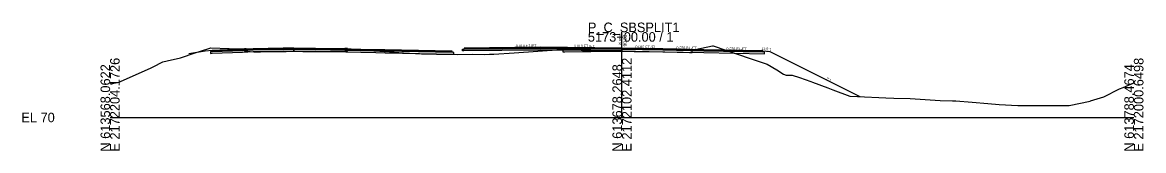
# Model space of a CAD drawing. Extents: x -26 to 1303, y -3010 to 12023.
# Drawn here: x -25.7 to 302.8, y 990.3 to 1027.8 of the extents above; entities that cross this region are included whole.
import ezdxf

# ---------------------------------------------------------------- set-up
doc = ezdxf.new("R2010")
doc.units = 0
for name, color, linetype in [('RD_GPK_XS_Cell', 7, 'Continuous'), ('RD_XS_Base', 7, 'Continuous'), ('RD_XS_ExGround', 7, 'Continuous'), ('RD_XS_ExPaveRet', 7, 'Continuous'), ('RD_XS_Greenside', 7, 'Continuous'), ('RD_XS_Pave', 7, 'Continuous'), ('RD_XS_PaveOvlay_CP', 7, 'Continuous'), ('RD_XS_TieSlope', 7, 'Continuous'), ('RD_XS_TX_Elev_EX', 7, 'Continuous'), ('RD_XS_TX_Elev_PR', 7, 'Continuous'), ('RD_XS_TX_ShdSlope', 7, 'Continuous'), ('RD_XS_TX_Slope', 7, 'Continuous')]:
    doc.layers.add(name, color=color, linetype=linetype)

msp = doc.modelspace()

# ---------------------------------------------------------------- linework, layer by layer
at = {"layer": 'RD_GPK_XS_Cell'}
for p, q in [((150, 1000), (150, 1025)), ((0, 1000), (150, 1000)), ((150, 1000), (300, 1000))]:
    msp.add_line(p, q, dxfattribs=at)
at = {"layer": 'RD_XS_Base'}
for p, q in [((29.75, 1019.29), (29.38, 1019.28)), ((29.38, 1019.28), (29.38, 1019.15)), ((29.38, 1019.15), (29.38, 1018.78)), ((29.38, 1018.78), (29.75, 1018.79)), ((29.88, 1019.3), (29.75, 1019.29)), ((29.75, 1018.79), (29.88, 1018.8)), ((38.75, 1019.65), (29.88, 1019.3)), ((29.88, 1018.8), (38.75, 1019.15)), ((41.88, 1019.78), (38.75, 1019.65)), ((38.75, 1019.15), (41.88, 1019.28)), ((50.75, 1019.95), (41.88, 1019.78)), ((41.88, 1019.28), (50.75, 1019.45)), ((53.88, 1020.02), (50.75, 1019.95)), ((50.75, 1019.45), (53.88, 1019.52)), ((53.88, 1020.13), (53.88, 1020.17)), ((53.88, 1020.17), (53.88, 1020)), ((53.88, 1020.02), (53.88, 1020.13)), ((53.88, 1019.89), (53.88, 1020.02)), ((60.14, 1019.89), (53.88, 1020.02)), ((53.88, 1020), (53.88, 1019.52)), ((53.88, 1019.52), (53.88, 1019.89)), ((53.88, 1019.52), (60.14, 1019.39)), ((77.88, 1019.54), (60.14, 1019.89)), ((60.14, 1019.39), (77.88, 1019.04)), ((80.5, 1019.48), (77.89, 1019.54)), ((77.9, 1019.04), (80.64, 1018.98)), ((100.23, 1019.09), (80.5, 1019.48)), ((80.64, 1018.98), (100.72, 1018.58)), ((100.36, 1019.09), (100.23, 1019.09)), ((100.72, 1019.08), (100.36, 1019.09)), ((100.72, 1018.94), (100.72, 1019.08)), ((100.72, 1018.58), (100.72, 1018.94)), ((103.22, 1019.52), (103.22, 1020.02)), ((103.22, 1020.02), (103.71, 1020.02)), ((103.7, 1019.52), (103.22, 1019.52)), ((125.98, 1019.75), (103.7, 1019.52)), ((103.71, 1020.02), (125.99, 1020.25)), ((126, 1020.25), (150, 1020.01)), ((126, 1020.25), (126, 1020.25)), ((126, 1020.25), (126, 1020.25)), ((150, 1019.51), (126, 1019.75)), ((126, 1019.75), (126, 1019.75)), ((126, 1019.75), (126, 1019.75)), ((150, 1020.01), (150, 1020.17)), ((150, 1020.17), (150, 1020.17)), ((150, 1020.17), (150, 1020.17)), ((150, 1020.17), (150, 1019.51)), ((150, 1020.01), (150, 1020.01)), ((162, 1019.77), (150, 1020.01)), ((150, 1020.01), (150, 1020.01)), ((150, 1020.01), (150, 1019.51)), ((150, 1019.51), (150, 1019.51)), ((150, 1019.51), (162, 1019.27)), ((174, 1019.53), (162, 1019.77)), ((162, 1019.77), (162, 1019.77)), ((162, 1019.27), (162, 1019.27)), ((162, 1019.27), (174, 1019.03)), ((191.3, 1019.19), (174, 1019.53)), ((174, 1019.53), (174, 1019.53)), ((174, 1019.03), (174, 1019.03)), ((174, 1019.03), (191.8, 1018.68)), ((191.8, 1019.18), (191.3, 1019.19)), ((191.3, 1019.19), (191.3, 1019.19)), ((191.8, 1018.68), (191.8, 1019.18)), ((191.8, 1019.18), (191.8, 1019.18))]:
    msp.add_line(p, q, dxfattribs=at)
at = {"layer": 'RD_XS_ExGround'}
msp.add_lwpolyline([(0, 1009.86), (2.62, 1010.37), (3.24, 1010.65), (11.83, 1014.45), (12.23, 1014.64), (12.65, 1014.83), (15.44, 1016.26), (16.77, 1016.62), (20.64, 1017.51), (24.89, 1018.92), (26.45, 1019.4), (29.47, 1020.36), (34.92, 1020.2), (39.37, 1020.15), (41.07, 1020.04), (42.59, 1019.97), (47.02, 1020.03), (53.91, 1020.14), (61.71, 1020.08), (66.5, 1020.07), (67.45, 1020.12), (69.53, 1020.18), (77.29, 1019.52), (77.67, 1019.5), (86.02, 1018.98), (91.26, 1018.65), (95.6, 1018.5), (101.76, 1018.43), (106.28, 1018.5), (109.72, 1018.49), (111.21, 1018.51), (112.45, 1018.58), (118.41, 1018.89), (132.32, 1019.94), (132.68, 1019.96), (133.03, 1019.97), (133.21, 1019.97), (138.46, 1020.04), (140.87, 1020.05), (150.39, 1020.15), (153.6, 1020.11), (162.51, 1020.02), (169.75, 1019.82), (170.53, 1019.79), (171.44, 1019.88), (176.54, 1020.99), (176.75, 1021.03), (187.51, 1017.23), (189.94, 1016.46), (192.57, 1015.63), (195.42, 1013.92), (197.34, 1012.73), (198.09, 1012.37), (199.91, 1012.39), (202, 1011.69), (205.32, 1010.5), (205.8, 1010.37), (210.29, 1008.73), (211.74, 1008.14), (216.75, 1006.29), (219.05, 1006.16), (227.27, 1005.78), (229.67, 1005.65), (234.45, 1005.55), (243.2, 1005.01), (246.85, 1004.9), (247.8, 1004.91), (252.6, 1004.47), (257.16, 1004.1), (260.56, 1003.81), (265.96, 1003.49), (266.03, 1003.48), (266.14, 1003.48), (266.57, 1003.47), (269.76, 1003.47), (277.89, 1003.47), (281.06, 1003.47), (287.19, 1004.78), (287.31, 1004.83), (291.24, 1006.04), (295.74, 1008.38), (296.85, 1008.74), (299.99, 1010.18), (300, 1010.19)], dxfattribs=at)
at = {"layer": 'RD_XS_ExPaveRet'}
for points in [[(67.45, 1020.12), (66.81, 1020.08), (66.5, 1020.07), (64.92, 1020.07), (61.71, 1020.08), (56.48, 1020.12), (53.91, 1020.14), (51.63, 1020.11), (47.02, 1020.03), (44.11, 1019.99), (42.59, 1019.97), (42.07, 1020), (41.07, 1020.04), (39.88, 1020.12), (39.37, 1020.15), (39.37, 1020.15), (39.37, 1020.15), (39.37, 1019.74), (39.37, 1019.4), (39.37, 1019.4), (39.37, 1019.4), (39.88, 1019.37), (41.07, 1019.29), (42.07, 1019.25), (42.59, 1019.22), (44.11, 1019.24), (47.02, 1019.28), (51.63, 1019.35), (53.91, 1019.39), (56.48, 1019.37), (61.71, 1019.33), (64.92, 1019.32), (66.5, 1019.32), (66.81, 1019.33), (67.45, 1019.37), (68.77, 1019.41), (69.53, 1019.43), (69.53, 1019.84), (69.53, 1020.18), (68.77, 1020.16), (67.45, 1020.12)], [(67.45, 1020.12), (66.81, 1020.08), (66.5, 1020.07), (64.92, 1020.07), (61.71, 1020.08), (56.48, 1020.12), (53.91, 1020.14), (51.63, 1020.11), (47.02, 1020.03), (44.11, 1019.99), (42.59, 1019.97), (42.07, 1020), (41.07, 1020.04), (39.88, 1020.12), (39.37, 1020.15), (39.37, 1020.15), (39.37, 1019.74), (39.37, 1019.4), (39.37, 1019.4), (39.88, 1019.37), (41.07, 1019.29), (42.07, 1019.25), (42.59, 1019.22), (44.11, 1019.24), (47.02, 1019.28), (51.63, 1019.35), (53.91, 1019.39), (56.48, 1019.37), (61.71, 1019.33), (64.92, 1019.32), (66.5, 1019.32), (66.81, 1019.33), (67.45, 1019.37), (68.77, 1019.41), (69.53, 1019.43), (69.53, 1019.84), (69.53, 1020.18), (68.77, 1020.16), (67.45, 1020.12)], [(170.53, 1019.79), (169.75, 1019.82), (169.75, 1019.82), (162.51, 1020.02), (153.6, 1020.11), (153.6, 1020.11), (150.39, 1020.15), (150.39, 1020.15), (140.87, 1020.05), (140.87, 1020.05), (138.46, 1020.04), (138.46, 1020.04), (138.46, 1020.04), (133.21, 1019.97), (133.21, 1019.97), (133.21, 1019.97), (133.03, 1019.97), (132.68, 1019.96), (132.68, 1019.96), (132.68, 1019.96), (132.68, 1019.21), (132.68, 1019.21), (133.03, 1019.22), (133.21, 1019.22), (133.21, 1019.22), (133.21, 1019.22), (138.46, 1019.29), (138.46, 1019.29), (138.46, 1019.29), (140.87, 1019.3), (140.87, 1019.3), (150.39, 1019.4), (150.39, 1019.4), (153.6, 1019.36), (153.6, 1019.36), (162.51, 1019.27), (169.75, 1019.07), (169.75, 1019.07), (170.53, 1019.04), (170.53, 1019.04), (170.53, 1019.79), (170.53, 1019.79), (170.53, 1019.79)], [(170.53, 1019.79), (169.75, 1019.82), (162.51, 1020.02), (153.6, 1020.11), (150.39, 1020.15), (140.87, 1020.05), (138.46, 1020.04), (133.21, 1019.97), (133.03, 1019.97), (132.68, 1019.96), (132.68, 1019.96), (132.68, 1019.21), (132.68, 1019.21), (133.03, 1019.22), (133.21, 1019.22), (138.46, 1019.29), (140.87, 1019.3), (150.39, 1019.4), (153.6, 1019.36), (162.51, 1019.27), (169.75, 1019.07), (170.53, 1019.04), (170.53, 1019.04), (170.53, 1019.79), (170.53, 1019.79)]]:
    msp.add_lwpolyline(points, dxfattribs=at)
at = {"layer": 'RD_XS_Greenside'}
for p, q in [((27.88, 1019.45), (23.03, 1018.65)), ((193.3, 1019.34), (219.72, 1006.13))]:
    msp.add_line(p, q, dxfattribs=at)
at = {"layer": 'RD_XS_Pave'}
for p, q in [((38.75, 1019.97), (29.88, 1019.61)), ((38.75, 1019.81), (29.88, 1019.45)), ((29.88, 1019.45), (38.75, 1019.81)), ((29.88, 1019.3), (38.75, 1019.65)), ((29.88, 1019.61), (29.88, 1019.57)), ((29.88, 1019.57), (29.88, 1019.45)), ((29.88, 1019.45), (29.88, 1019.41)), ((29.88, 1019.41), (29.88, 1019.3)), ((41.88, 1020.09), (38.75, 1019.97)), ((41.88, 1019.93), (38.75, 1019.81)), ((38.75, 1019.81), (41.88, 1019.93)), ((38.75, 1019.65), (41.88, 1019.78)), ((50.75, 1020.27), (41.88, 1020.09)), ((50.75, 1020.11), (41.88, 1019.93)), ((41.88, 1019.93), (50.75, 1020.11)), ((41.88, 1019.78), (50.75, 1019.95)), ((53.88, 1020.33), (50.75, 1020.27)), ((53.88, 1020.17), (50.75, 1020.11)), ((50.75, 1020.11), (53.88, 1020.17)), ((50.75, 1019.95), (53.88, 1020.02)), ((60.14, 1020.21), (53.88, 1020.33)), ((53.88, 1020.13), (53.88, 1020.17)), ((53.88, 1020.17), (60.14, 1020.05)), ((60.14, 1020.05), (53.88, 1020.17)), ((53.88, 1020.17), (53.88, 1020.13)), ((53.88, 1020.02), (53.88, 1020.13)), ((53.88, 1020.13), (53.88, 1020.02)), ((53.88, 1020.02), (60.14, 1019.89)), ((77.88, 1019.85), (60.14, 1020.21)), ((60.14, 1020.05), (77.88, 1019.69)), ((77.88, 1019.69), (60.14, 1020.05)), ((60.14, 1019.89), (77.88, 1019.54)), ((80.49, 1019.8), (77.88, 1019.85)), ((77.88, 1019.69), (80.49, 1019.64)), ((80.49, 1019.64), (77.88, 1019.69)), ((77.89, 1019.54), (80.5, 1019.48)), ((100.22, 1019.41), (80.49, 1019.8)), ((80.49, 1019.64), (100.23, 1019.25)), ((100.23, 1019.25), (80.49, 1019.64)), ((80.5, 1019.48), (100.23, 1019.09)), ((100.22, 1019.37), (100.22, 1019.41)), ((100.22, 1019.25), (100.22, 1019.37)), ((100.22, 1019.21), (100.22, 1019.25)), ((100.22, 1019.09), (100.22, 1019.21)), ((103.71, 1020.02), (125.99, 1020.25)), ((126, 1020.56), (103.72, 1020.34)), ((126, 1020.4), (103.72, 1020.18)), ((103.72, 1020.18), (126, 1020.4)), ((103.72, 1020.34), (103.72, 1020.18)), ((103.72, 1020.18), (103.72, 1020.02)), ((150, 1020.33), (126, 1020.56)), ((126, 1020.56), (126, 1020.56)), ((126, 1020.56), (126, 1020.56)), ((150, 1020.17), (126, 1020.4)), ((126, 1020.4), (126, 1020.4)), ((126, 1020.4), (126, 1020.4)), ((126, 1020.4), (126, 1020.4)), ((126, 1020.4), (126, 1020.4)), ((126, 1020.4), (150, 1020.17)), ((126, 1020.25), (126, 1020.25)), ((126, 1020.25), (126, 1020.25)), ((126, 1020.25), (150, 1020.01)), ((162, 1020.09), (150, 1020.33)), ((150, 1020.33), (150, 1020.33)), ((150, 1020.01), (150, 1020.17)), ((150, 1020.17), (150, 1020.17)), ((150, 1020.17), (150, 1020.17)), ((150, 1020.17), (162, 1019.93)), ((162, 1019.93), (150, 1020.17)), ((150, 1020.17), (150, 1020.17)), ((150, 1020.17), (150, 1020.17)), ((150, 1020.17), (150, 1020.01)), ((150, 1020.01), (150, 1020.01)), ((150, 1020.01), (162, 1019.77)), ((174, 1019.85), (162, 1020.09)), ((162, 1020.09), (162, 1020.09)), ((162, 1019.93), (162, 1019.93)), ((162, 1019.93), (174, 1019.69)), ((174, 1019.69), (162, 1019.93)), ((162, 1019.93), (162, 1019.93)), ((162, 1019.77), (162, 1019.77)), ((162, 1019.77), (174, 1019.53)), ((191.3, 1019.5), (174, 1019.85)), ((174, 1019.85), (174, 1019.85)), ((174, 1019.69), (174, 1019.69)), ((174, 1019.69), (191.3, 1019.34)), ((191.3, 1019.34), (174, 1019.69)), ((174, 1019.69), (174, 1019.69)), ((174, 1019.53), (191.3, 1019.19)), ((174, 1019.53), (174, 1019.53)), ((191.3, 1019.34), (191.3, 1019.5)), ((191.3, 1019.5), (191.3, 1019.5)), ((191.3, 1019.19), (191.3, 1019.34)), ((191.3, 1019.34), (191.3, 1019.34))]:
    msp.add_line(p, q, dxfattribs=at)
at = {"layer": 'RD_XS_PaveOvlay_CP'}
for p, q in [((29.88, 1019.61), (41.88, 1020.09)), ((41.88, 1020.09), (53.88, 1020.33)), ((53.88, 1020.33), (77.88, 1019.85)), ((77.88, 1019.85), (100.22, 1019.41)), ((126, 1020.56), (103.72, 1020.34)), ((150, 1020.33), (126, 1020.56)), ((126, 1020.56), (126, 1020.56)), ((126, 1020.56), (126, 1020.56)), ((162, 1020.09), (150, 1020.33)), ((150, 1020.33), (150, 1020.33)), ((174, 1019.85), (162, 1020.09)), ((162, 1020.09), (162, 1020.09)), ((191.3, 1019.5), (174, 1019.85)), ((174, 1019.85), (174, 1019.85))]:
    msp.add_line(p, q, dxfattribs=at)
at = {"layer": 'RD_XS_TieSlope'}
for p, q in [((29.88, 1019.61), (27.88, 1019.45)), ((191.3, 1019.5), (193.3, 1019.34))]:
    msp.add_line(p, q, dxfattribs=at)

# ---------------------------------------------------------------- texts
at = {"layer": 'RD_GPK_XS_Cell'}
for s, p in [('5173+00.00 / 1', (140, 1022.2)), ('P_C_SBSPLIT1', (140, 1025)), ('EL 70', (-26, 998.6))]:
    msp.add_text(s, height=2.8, dxfattribs=at).set_placement(p)
for s, p in [('N 613568.0622', (0, 990)), ('E 2172204.1726', (2.8, 990)), ('N 613678.2648', (150, 990)), ('E 2172102.4112', (152.8, 990)), ('N 613788.4674', (300, 990)), ('E 2172000.6498', (302.8, 990))]:
    msp.add_text(s, height=2.8, rotation=90, dxfattribs=at).set_placement(p)
at = {"layer": 'RD_XS_TX_Elev_EX'}
msp.add_text('90.14', height=0.6, rotation=90, dxfattribs=at).set_placement((149.68, 1021.26))
at = {"layer": 'RD_XS_TX_Elev_PR'}
msp.add_text('90.33', height=1, rotation=90, dxfattribs=at).set_placement((151.35, 1020.81))
at = {"layer": 'RD_XS_TX_ShdSlope'}
msp.add_text('12.5:1', height=0.75, rotation=355.4261, dxfattribs=at).set_placement((190.84, 1019.82))
at = {"layer": 'RD_XS_TX_Slope'}
for s, rotation, p in [('0.010 FT./FT.', 0.5729, (118.93, 1020.59)), ('0.010 FT./FT.', 359.4413, (135.94, 1020.57)), ('0.020 FT./FT.', 358.8542, (153.94, 1020.35)), ('0.020 FT./FT.', 358.8542, (165.94, 1020.11)), ('0.020 FT./FT.', 358.8542, (180.59, 1019.82)), ('2:1', 333.4349, (209.81, 1011.15))]:
    msp.add_text(s, height=0.75, rotation=rotation, dxfattribs=at).set_placement(p)

doc.saveas('drawing.dxf')
